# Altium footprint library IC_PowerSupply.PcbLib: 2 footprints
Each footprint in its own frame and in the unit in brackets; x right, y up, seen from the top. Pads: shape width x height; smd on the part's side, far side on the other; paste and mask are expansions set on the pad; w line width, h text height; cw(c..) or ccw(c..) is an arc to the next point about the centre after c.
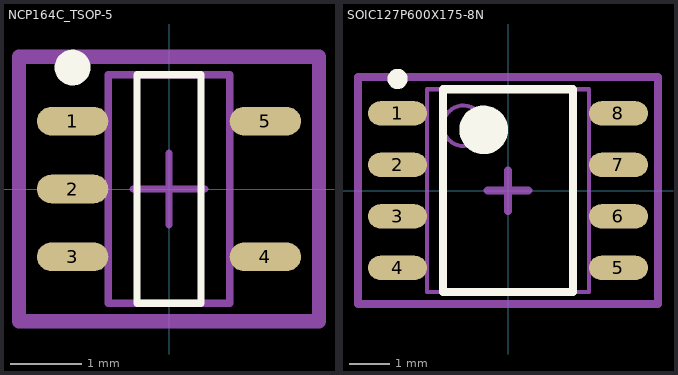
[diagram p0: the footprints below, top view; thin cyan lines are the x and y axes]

## NCP164C_TSOP-5 [mm] "TSOP, 6-Leads, Body 3.00x1.50mm, Pitch 0.95mm, IPC Medium Density"
height 1.1
pads (5):
  oval 1x0.4 smd: 1(-1.35,0.95) 2(-1.35,0) 3(-1.35,-0.95) 4(1.35,-0.95) 5(1.35,0.95)
Top Overlay:
  circle w0.25: c-1.35,1.7 r0.125
  lines w0.1: -0.45,-1.6 -0.45,1.6 0.45,1.6 0.45,-1.6 -0.45,-1.6
Mechanical 13:
  lines w0.1: -0.85,-1.6 -0.85,1.6 0.85,1.6 0.85,-1.6 -0.85,-1.6
Mechanical 15:
  lines w0.1: -0.5,0 0.5,0 ; 0,-0.5 0,0.5
  lines w0.2: -2.1,-1.85 -2.1,1.85 2.1,1.85 2.1,-1.85 -2.1,-1.85
3D body "User Library-5-TSOP.step": height 1.1, standoff 0, extent -1.5,-1.55 1.5,1.55

## SOIC127P600X175-8N [mm] "SOIC, 8-Leads, Body 4.90x3.90mm, Pitch 1.27mm, IPC Medium Density"
height 1.75
pads (8):
  oval 1.45x0.6 smd: 1(-2.725,1.905) 2(-2.725,0.635) 3(-2.725,-0.635) 4(-2.725,-1.905) 5(2.725,-1.905) 6(2.725,-0.635) 7(2.725,0.635) 8(2.725,1.905)
Top Overlay:
  circle w0.25: c-2.725,2.755 r0.125
  circle w0.6: c-0.6,1.5 r0.3
  lines w0.2: -1.6,-2.5 -1.6,2.5 1.6,2.5 1.6,-2.5 -1.6,-2.5
Mechanical 13:
  circle w0.1: c-1.1,1.6 r0.5
  lines w0.1: -2,-2.5 -2,2.5 2,2.5 2,-2.5 -2,-2.5
Mechanical 15:
  lines w0.2: -0.5,0 0.5,0 ; 0,-0.5 0,0.5 ; -3.7,-2.8 -3.7,2.8 3.7,2.8 3.7,-2.8 -3.7,-2.8
3D body "SOIC127P600X175-8N.step": height 1.75, standoff 0, extent -2.997,-2.5 2.997,2.5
